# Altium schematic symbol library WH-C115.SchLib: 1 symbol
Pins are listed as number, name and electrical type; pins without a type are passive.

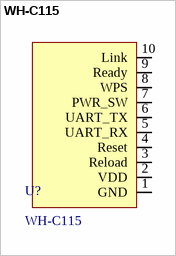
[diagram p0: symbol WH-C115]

## WH-C115
designator U?
pins: 1 GND, 2 VDD, 3 Reload, 4 Reset, 5 UART_RX, 6 UART_TX, 7 PWR_SW, 8 WPS, 9 Ready, 10 Link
